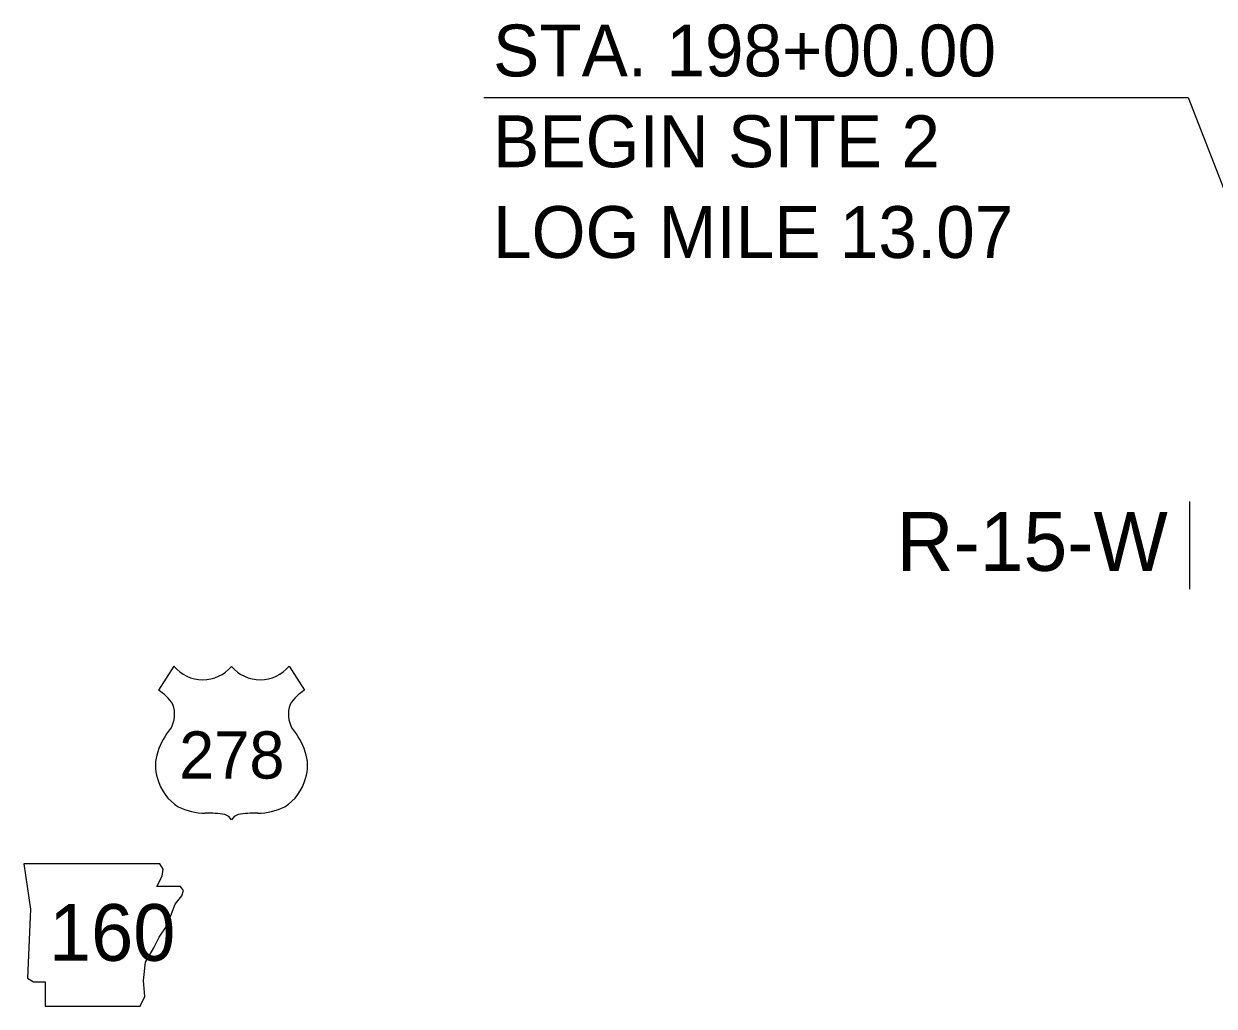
# Model space of a CAD drawing. Extents: x 172 to 3385, y 73 to 2074.
# Drawn here: x 862.5 to 1266.8, y 1198.6 to 1532.2 of the extents above; entities that cross this region are included whole.
import ezdxf

# ---------------------------------------------------------------- set-up
doc = ezdxf.new("R2010")
doc.units = 0
for name, color, linetype in [('Default', 7, 'Continuous'), ('Level 21', 7, 'Continuous'), ('Level 22', 7, 'Continuous'), ('R_Border', 7, 'Continuous')]:
    doc.layers.add(name, color=color, linetype=linetype)

msp = doc.modelspace()

# ---------------------------------------------------------------- linework, layer by layer
at = {"layer": 'Default'}
msp.add_line((1258.45, 1369.97), (1258.45, 1340.23), dxfattribs=at)
at = {"layer": 'Level 21'}
msp.add_lwpolyline([(862.48, 1246.96), (864.79, 1231.54), (863.76, 1208.16), (865.82, 1206.87), (869.68, 1206.87), (869.68, 1198.65), (902.05, 1198.65), (903.59, 1201.99), (903.08, 1207.39), (903.85, 1213.55), (906.68, 1218.44), (908.48, 1222.03), (911.05, 1225.89), (912.59, 1230), (913.87, 1233.34), (916.19, 1236.17), (916.7, 1237.96), (915.67, 1239.25), (907.71, 1239.25), (909.5, 1242.85), (909.76, 1245.16), (908.7, 1246.94)], close=True, dxfattribs=at)
at = {"layer": 'Level 22'}
for p, q in [((913.48, 1314.06), (908.22, 1305.93)), ((952.57, 1314.06), (957.83, 1305.93))]:
    msp.add_line(p, q, dxfattribs=at)
for centre, radius, start, end in [((923.27, 1322.3), 12.8, 220.075, 319.6701), ((942.78, 1322.3), 12.8, 220.3299, 319.925), ((901.35, 1294.13), 13.66, 30.7809, 59.9883), ((964.7, 1294.13), 13.66, 120.0117, 149.2191), ((904.36, 1297.73), 9.36, 328.8105, 21.2108), ((961.69, 1297.73), 9.36, 158.7892, 211.1895), ((928.84, 1278.54), 21.85, 138.9565, 162.6913), ((937.21, 1278.54), 21.85, 17.3087, 41.0435), ((921.63, 1280.33), 14.44, 160.9576, 197.3819), ((944.42, 1280.33), 14.44, 342.6181, 19.0424), ((923.98, 1280.37), 16.7, 195.1074, 237.1312), ((942.07, 1280.37), 16.7, 302.8688, 344.8926), ((924.29, 1285.63), 21.45, 244.0771, 269.5779), ((941.76, 1285.63), 21.45, 270.4221, 295.9229), ((924.79, 1224.9), 39.29, 81.1942, 90.9539), ((929.7, 1260.12), 3.76, 28.0342, 72.9864), ((936.35, 1260.12), 3.76, 107.0136, 151.9658), ((941.26, 1224.9), 39.29, 89.0461, 98.8058)]:
    msp.add_arc(centre, radius, start, end, dxfattribs=at)
at = {"layer": 'R_Border'}
msp.add_lwpolyline([(1018.72, 1507.24), (1257.92, 1507.16), (1310.86, 1371.59)], dxfattribs=at)

# ---------------------------------------------------------------- texts
at = {"layer": 'Default'}
msp.add_text('R-15-W', height=20, dxfattribs=at).set_placement((1158.94, 1346.47))
at = {"layer": 'Level 21'}
msp.add_text('160', height=19.247, dxfattribs=at).set_placement((871.02, 1214.06))
at = {"layer": 'Level 22'}
msp.add_text('278', height=16.04, dxfattribs=at).set_placement((915.23, 1275.93))
at = {"layer": 'R_Border'}
for s, p in [('STA. 198+00.00', (1021.86, 1514.36)), ('BEGIN SITE 2', (1021.86, 1483.54)), ('LOG MILE 13.07', (1021.86, 1452.72))]:
    msp.add_text(s, height=17.61, dxfattribs=at).set_placement(p)

doc.saveas('drawing.dxf')
